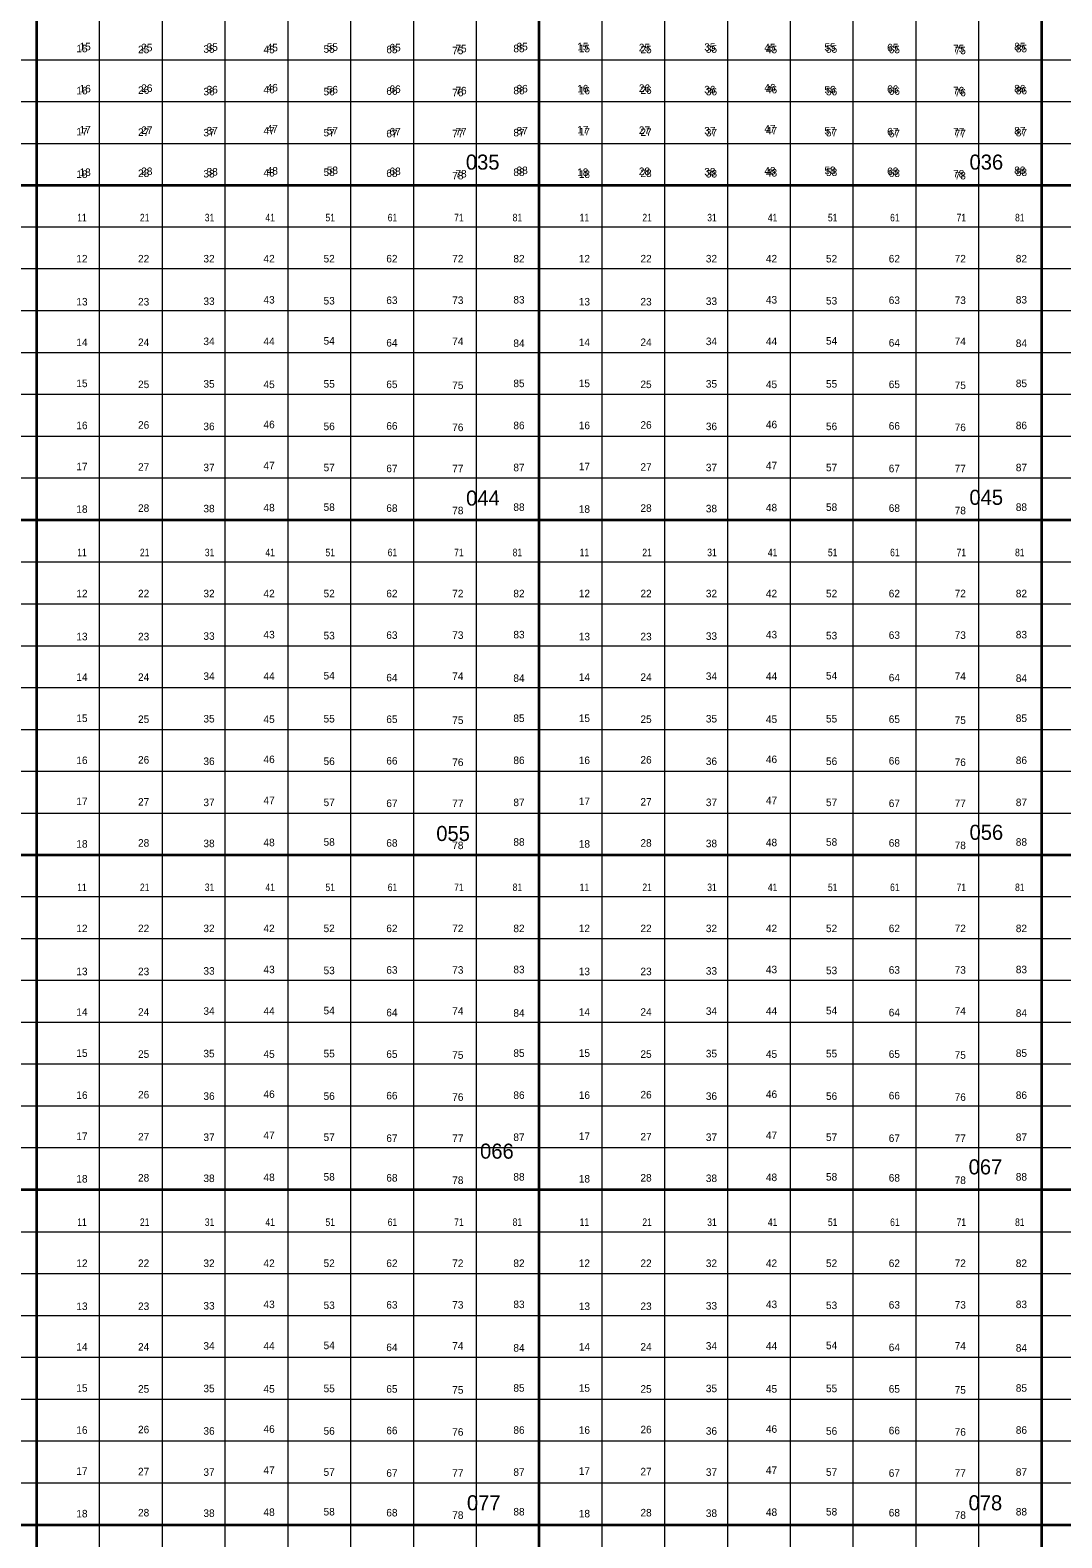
# Model space of a CAD drawing. Extents: x 639000 to 672000, y 222000 to 252000.
# Drawn here: x 647960 to 654120, y 233921 to 242926 of the extents above; entities that cross this region are included whole.
import ezdxf
from ezdxf.enums import TextEntityAlignment as Align

# ---------------------------------------------------------------- set-up
doc = ezdxf.new("R2010")
doc.units = 0
doc.header["$LTSCALE"] = 18
doc.layers.add('1', color=7, linetype='Continuous', lineweight=13)
doc.layers.add('2', color=7, linetype='Continuous')
doc.layers.add('29', color=7, linetype='Continuous')

msp = doc.modelspace()

# ---------------------------------------------------------------- linework, layer by layer
at = {"layer": '1', "lineweight": 35}
for p, q in [((648000, 224000), (648000, 252000)), ((651000, 224000), (651000, 252000)), ((654000, 222000), (654000, 252000)), ((639000, 242000), (672000, 242000)), ((672000, 240000), (639000, 240000)), ((639000, 238000), (672000, 238000)), ((672000, 236000), (639000, 236000)), ((639000, 234000), (672000, 234000))]:
    msp.add_line(p, q, dxfattribs=at)
at = {"layer": '1'}
for p, q in [((648375, 224000), (648375, 252000)), ((648750, 224000), (648750, 252000)), ((649125, 224000), (649125, 252000)), ((649500, 224000), (649500, 252000)), ((649875, 224000), (649875, 252000)), ((650250, 224000), (650250, 252000)), ((650625, 224000), (650625, 252000)), ((651375, 224000), (651375, 252000)), ((651750, 224000), (651750, 252000)), ((652125, 224000), (652125, 252000)), ((652500, 224000), (652500, 252000)), ((652875, 224000), (652875, 252000)), ((653250, 224000), (653250, 252000)), ((653625, 224000), (653625, 252000)), ((639000, 242750), (666000, 242750)), ((639000, 242500), (666000, 242500)), ((639000, 242250), (666000, 242250)), ((672000, 241750), (639000, 241750)), ((672000, 241500), (639000, 241500)), ((672000, 241250), (639000, 241250)), ((672000, 241000), (639000, 241000)), ((672000, 240750), (639000, 240750)), ((672000, 240500), (639000, 240500)), ((672000, 240250), (639000, 240250)), ((639000, 239750), (672000, 239750)), ((639000, 239500), (672000, 239500)), ((639000, 239250), (672000, 239250)), ((639000, 239000), (672000, 239000)), ((639000, 238750), (672000, 238750)), ((639000, 238500), (672000, 238500)), ((639000, 238250), (672000, 238250)), ((672000, 237750), (639000, 237750)), ((672000, 237500), (639000, 237500)), ((672000, 237250), (639000, 237250)), ((672000, 237000), (639000, 237000)), ((672000, 236750), (639000, 236750)), ((672000, 236500), (639000, 236500)), ((672000, 236250), (639000, 236250)), ((639000, 235750), (672000, 235750)), ((639000, 235500), (672000, 235500)), ((639000, 235250), (672000, 235250)), ((639000, 235000), (672000, 235000)), ((639000, 234750), (672000, 234750)), ((639000, 234500), (672000, 234500)), ((639000, 234250), (672000, 234250))]:
    msp.add_line(p, q, dxfattribs=at)

# ---------------------------------------------------------------- texts
at = {"layer": '2'}
for s, p in [('035', (650662.01, 242093.32)), ('055', (650485.32, 238083.33))]:
    msp.add_text(s, height=90, dxfattribs=at).set_placement(p, align=Align.CENTER)
for s, rotation, p in [('036', 359.94, (653669.39, 242093.33)), ('044', 0.36, (650663.7, 240086.93)), ('045', 359.94, (653668.72, 240091.12)), ('056', 359.94, (653669.39, 238090.28)), ('066', 359.94, (650746.84, 236186.08)), ('067', 359.94, (653664.01, 236092.18)), ('077', 359.94, (650668.28, 234085.86)), ('078', 359.94, (653663.61, 234085.86))]:
    msp.add_text(s, height=90, rotation=rotation, dxfattribs=at).set_placement(p, align=Align.CENTER)
at = {"layer": '29'}
for s, p in [('15', (648269.26, 242794.13)), ('15', (648288.31, 242805.68)), ('25', (648637.51, 242788.35)), ('25', (648656.57, 242799.9)), ('35', (649027.99, 242791.24)), ('35', (649047.04, 242802.79)), ('45', (649386.72, 242788.35)), ('45', (649405.77, 242799.9)), ('55', (649745.45, 242791.24)), ('55', (649764.5, 242802.79)), ('65', (650120.05, 242788.36)), ('65', (650139.11, 242799.9)), ('75', (650513.7, 242782.58)), ('75', (650532.76, 242794.13)), ('85', (650878.78, 242794.13)), ('85', (650897.84, 242805.68)), ('15', (651259.74, 242805.68)), ('15', (651269.26, 242794.13)), ('25', (651628, 242799.9)), ('25', (651637.51, 242788.35)), ('35', (652018.47, 242802.79)), ('35', (652027.99, 242791.24)), ('45', (652377.2, 242799.9)), ('45', (652386.72, 242788.35)), ('55', (652735.94, 242802.79)), ('55', (652745.45, 242791.24)), ('65', (653110.54, 242799.9)), ('65', (653120.05, 242788.36)), ('75', (653504.19, 242794.13)), ('75', (653513.7, 242782.58)), ('85', (653869.27, 242805.68)), ('85', (653878.78, 242794.13)), ('16', (648288.31, 242554.51)), ('26', (648656.57, 242557.4)), ('36', (649047.04, 242548.74)), ('46', (649386.72, 242548.74)), ('46', (649405.77, 242560.29)), ('56', (649764.5, 242548.74)), ('66', (650139.11, 242551.62)), ('86', (650897.84, 242554.51)), ('16', (651259.74, 242554.51)), ('26', (651628, 242557.4)), ('36', (652018.47, 242548.74)), ('46', (652377.2, 242560.29)), ('46', (652386.72, 242548.74)), ('56', (652735.94, 242548.74)), ('66', (653110.54, 242551.62)), ('86', (653869.27, 242554.51)), ('16', (648269.26, 242542.96)), ('26', (648637.51, 242545.85)), ('36', (649027.99, 242537.19)), ('56', (649745.45, 242537.19)), ('66', (650120.05, 242540.08)), ('76', (650513.7, 242531.42)), ('76', (650532.76, 242542.96)), ('86', (650878.78, 242542.96)), ('16', (651269.26, 242542.96)), ('26', (651637.51, 242545.85)), ('36', (652027.99, 242537.19)), ('56', (652745.45, 242537.19)), ('66', (653120.05, 242540.08)), ('76', (653504.19, 242542.96)), ('76', (653513.7, 242531.42)), ('86', (653878.78, 242542.96)), ('17', (648269.26, 242297.57)), ('17', (648288.31, 242309.12)), ('27', (648637.51, 242294.69)), ('27', (648656.57, 242306.23)), ('37', (649027.99, 242291.8)), ('37', (649047.04, 242303.35)), ('47', (649386.72, 242303.35)), ('47', (649405.77, 242314.9)), ('57', (649745.45, 242291.8)), ('57', (649764.5, 242303.35)), ('67', (650120.05, 242286.03)), ('67', (650139.11, 242297.57)), ('77', (650513.7, 242286.03)), ('77', (650532.76, 242297.57)), ('87', (650878.78, 242291.8)), ('87', (650897.84, 242303.35)), ('17', (651259.74, 242309.12)), ('17', (651269.26, 242297.57)), ('27', (651628, 242306.23)), ('27', (651637.51, 242294.69)), ('37', (652018.47, 242303.35)), ('37', (652027.99, 242291.8)), ('47', (652377.21, 242314.9)), ('47', (652386.72, 242303.35)), ('57', (652735.94, 242303.35)), ('57', (652745.45, 242291.8)), ('67', (653110.54, 242297.57)), ('67', (653120.05, 242286.03)), ('77', (653504.19, 242297.57)), ('77', (653513.7, 242286.03)), ('87', (653869.27, 242303.35)), ('87', (653878.78, 242291.8)), ('18', (648269.25, 242043.52)), ('18', (648288.31, 242055.07)), ('28', (648637.51, 242049.3)), ('28', (648656.57, 242060.84)), ('38', (649027.99, 242046.41)), ('38', (649047.04, 242057.96)), ('48', (649386.72, 242052.18)), ('48', (649405.77, 242063.73)), ('58', (649745.45, 242055.07)), ('58', (649764.5, 242066.62)), ('68', (650120.05, 242049.3)), ('68', (650139.11, 242060.84)), ('78', (650513.7, 242034.86)), ('78', (650532.76, 242046.41)), ('88', (650878.78, 242055.07)), ('88', (650897.84, 242066.62)), ('18', (651259.74, 242055.07)), ('18', (651269.25, 242043.52)), ('28', (651628, 242060.84)), ('28', (651637.51, 242049.3)), ('38', (652018.47, 242057.96)), ('38', (652027.99, 242046.41)), ('48', (652377.2, 242063.73)), ('48', (652386.72, 242052.18)), ('58', (652735.93, 242066.62)), ('58', (652745.45, 242055.07)), ('68', (653110.54, 242060.84)), ('68', (653120.05, 242049.3)), ('78', (653504.19, 242046.41)), ('78', (653513.7, 242034.86)), ('88', (653869.27, 242066.62)), ('88', (653878.78, 242055.07)), ('12', (648269.25, 241538.96)), ('22', (648637.51, 241538.96)), ('32', (649027.99, 241538.96)), ('42', (649386.72, 241538.96)), ('52', (649745.45, 241538.96)), ('62', (650120.05, 241538.96)), ('72', (650513.7, 241538.96)), ('82', (650878.78, 241538.96)), ('12', (651269.25, 241538.96)), ('22', (651637.51, 241538.96)), ('32', (652027.99, 241538.96)), ('42', (652386.72, 241538.96)), ('52', (652745.45, 241538.96)), ('62', (653120.05, 241538.96)), ('72', (653513.7, 241538.96)), ('82', (653878.78, 241538.96)), ('43', (649386.72, 241293.57)), ('53', (649745.45, 241287.8)), ('63', (650120.05, 241290.68)), ('73', (650513.7, 241290.68)), ('83', (650878.78, 241293.57)), ('43', (652386.72, 241293.57)), ('53', (652745.45, 241287.8)), ('63', (653120.05, 241290.68)), ('73', (653513.7, 241290.68)), ('83', (653878.78, 241293.57)), ('13', (648269.26, 241282.02)), ('23', (648637.51, 241282.02)), ('33', (649027.99, 241284.91)), ('13', (651269.26, 241282.02)), ('23', (651637.51, 241282.02)), ('33', (652027.99, 241284.91)), ('14', (648269.26, 241039.52)), ('24', (648637.51, 241039.52)), ('34', (649027.99, 241045.29)), ('44', (649386.72, 241045.29)), ('54', (649745.45, 241048.18)), ('64', (650120.05, 241036.63)), ('74', (650513.7, 241045.29)), ('84', (650878.78, 241033.74)), ('14', (651269.26, 241039.52)), ('24', (651637.51, 241039.52)), ('34', (652027.99, 241045.29)), ('44', (652386.72, 241045.29)), ('54', (652745.45, 241048.18)), ('64', (653120.05, 241036.63)), ('74', (653513.7, 241045.29)), ('84', (653878.78, 241033.74)), ('15', (648269.26, 240794.13)), ('25', (648637.51, 240788.35)), ('35', (649027.99, 240791.24)), ('45', (649386.72, 240788.35)), ('55', (649745.45, 240791.24)), ('65', (650120.05, 240788.36)), ('75', (650513.7, 240782.58)), ('85', (650878.78, 240794.13)), ('15', (651269.26, 240794.13)), ('25', (651637.51, 240788.35)), ('35', (652027.99, 240791.24)), ('45', (652386.72, 240788.35)), ('55', (652745.45, 240791.24)), ('65', (653120.05, 240788.36)), ('75', (653513.7, 240782.58)), ('85', (653878.78, 240794.13)), ('16', (648269.26, 240542.96)), ('26', (648637.51, 240545.85)), ('36', (649027.99, 240537.19)), ('46', (649386.72, 240548.74)), ('56', (649745.45, 240537.19)), ('66', (650120.05, 240540.08)), ('76', (650513.7, 240531.42)), ('86', (650878.78, 240542.96)), ('16', (651269.26, 240542.96)), ('26', (651637.51, 240545.85)), ('36', (652027.99, 240537.19)), ('46', (652386.72, 240548.74)), ('56', (652745.45, 240537.19)), ('66', (653120.05, 240540.08)), ('76', (653513.7, 240531.42)), ('86', (653878.78, 240542.96)), ('17', (648269.26, 240297.57)), ('47', (649386.72, 240303.35)), ('17', (651269.26, 240297.57)), ('47', (652386.72, 240303.35)), ('27', (648637.51, 240294.69)), ('37', (649027.99, 240291.8)), ('57', (649745.45, 240291.8)), ('67', (650120.05, 240286.03)), ('77', (650513.7, 240286.03)), ('87', (650878.78, 240291.8)), ('27', (651637.51, 240294.69)), ('37', (652027.99, 240291.8)), ('57', (652745.45, 240291.8)), ('67', (653120.05, 240286.03)), ('77', (653513.7, 240286.03)), ('87', (653878.78, 240291.8)), ('18', (648269.25, 240043.52)), ('28', (648637.51, 240049.3)), ('38', (649027.99, 240046.41)), ('48', (649386.72, 240052.18)), ('58', (649745.45, 240055.07)), ('68', (650120.05, 240049.3)), ('78', (650513.7, 240034.86)), ('88', (650878.78, 240055.07)), ('18', (651269.25, 240043.52)), ('28', (651637.51, 240049.3)), ('38', (652027.99, 240046.41)), ('48', (652386.72, 240052.18)), ('58', (652745.45, 240055.07)), ('68', (653120.05, 240049.3)), ('78', (653513.7, 240034.86)), ('88', (653878.78, 240055.07)), ('12', (648269.25, 239538.96)), ('22', (648637.51, 239538.96)), ('32', (649027.99, 239538.96)), ('42', (649386.72, 239538.96)), ('52', (649745.45, 239538.96)), ('62', (650120.05, 239538.96)), ('72', (650513.7, 239538.96)), ('82', (650878.78, 239538.96)), ('12', (651269.25, 239538.96)), ('22', (651637.51, 239538.96)), ('32', (652027.99, 239538.96)), ('42', (652386.72, 239538.96)), ('52', (652745.45, 239538.96)), ('62', (653120.05, 239538.96)), ('72', (653513.7, 239538.96)), ('82', (653878.78, 239538.96)), ('13', (648269.26, 239282.02)), ('23', (648637.51, 239282.02)), ('33', (649027.99, 239284.91)), ('43', (649386.72, 239293.57)), ('53', (649745.45, 239287.8)), ('63', (650120.05, 239290.68)), ('73', (650513.7, 239290.68)), ('83', (650878.78, 239293.57)), ('13', (651269.26, 239282.02)), ('23', (651637.51, 239282.02)), ('33', (652027.99, 239284.91)), ('43', (652386.72, 239293.57)), ('53', (652745.45, 239287.8)), ('63', (653120.05, 239290.68)), ('73', (653513.7, 239290.68)), ('83', (653878.78, 239293.57)), ('14', (648269.26, 239039.52)), ('24', (648637.51, 239039.52)), ('34', (649027.99, 239045.29)), ('44', (649386.72, 239045.29)), ('54', (649745.45, 239048.18)), ('64', (650120.05, 239036.63)), ('74', (650513.7, 239045.29)), ('14', (651269.26, 239039.52)), ('24', (651637.51, 239039.52)), ('34', (652027.99, 239045.29)), ('44', (652386.72, 239045.29)), ('54', (652745.45, 239048.18)), ('64', (653120.05, 239036.63)), ('74', (653513.7, 239045.29)), ('84', (650878.78, 239033.74)), ('84', (653878.78, 239033.74)), ('15', (648269.26, 238794.13)), ('25', (648637.51, 238788.35)), ('35', (649027.99, 238791.24)), ('45', (649386.72, 238788.35)), ('55', (649745.45, 238791.24)), ('65', (650120.05, 238788.36)), ('75', (650513.7, 238782.58)), ('85', (650878.78, 238794.13)), ('15', (651269.26, 238794.13)), ('25', (651637.51, 238788.35)), ('35', (652027.99, 238791.24)), ('45', (652386.72, 238788.35)), ('55', (652745.45, 238791.24)), ('65', (653120.05, 238788.36)), ('75', (653513.7, 238782.58)), ('85', (653878.78, 238794.13)), ('16', (648269.26, 238542.96)), ('26', (648637.51, 238545.85)), ('36', (649027.99, 238537.19)), ('46', (649386.72, 238548.74)), ('56', (649745.45, 238537.19)), ('66', (650120.05, 238540.08)), ('76', (650513.7, 238531.42)), ('86', (650878.78, 238542.96)), ('16', (651269.26, 238542.96)), ('26', (651637.51, 238545.85)), ('36', (652027.99, 238537.19)), ('46', (652386.72, 238548.74)), ('56', (652745.45, 238537.19)), ('66', (653120.05, 238540.08)), ('76', (653513.7, 238531.42)), ('86', (653878.78, 238542.96)), ('17', (648269.26, 238297.57)), ('27', (648637.51, 238294.69)), ('37', (649027.99, 238291.8)), ('47', (649386.72, 238303.35)), ('57', (649745.45, 238291.8)), ('67', (650120.05, 238286.03)), ('77', (650513.7, 238286.03)), ('87', (650878.78, 238291.8)), ('17', (651269.26, 238297.57)), ('27', (651637.51, 238294.69)), ('37', (652027.99, 238291.8)), ('47', (652386.72, 238303.35)), ('57', (652745.45, 238291.8)), ('67', (653120.05, 238286.03)), ('77', (653513.7, 238286.03)), ('87', (653878.78, 238291.8)), ('28', (648637.51, 238049.3)), ('38', (649027.99, 238046.41)), ('48', (649386.72, 238052.18)), ('58', (649745.45, 238055.07)), ('68', (650120.05, 238049.3)), ('88', (650878.78, 238055.07)), ('28', (651637.51, 238049.3)), ('38', (652027.99, 238046.41)), ('48', (652386.72, 238052.18)), ('58', (652745.45, 238055.07)), ('68', (653120.05, 238049.3)), ('88', (653878.78, 238055.07)), ('18', (648269.25, 238043.52)), ('78', (650513.7, 238034.86)), ('18', (651269.25, 238043.52)), ('78', (653513.7, 238034.86)), ('12', (648269.25, 237538.96)), ('22', (648637.51, 237538.96)), ('32', (649027.99, 237538.96)), ('42', (649386.72, 237538.96)), ('52', (649745.45, 237538.96)), ('62', (650120.05, 237538.96)), ('72', (650513.7, 237538.96)), ('82', (650878.78, 237538.96)), ('12', (651269.25, 237538.96)), ('22', (651637.51, 237538.96)), ('32', (652027.99, 237538.96)), ('42', (652386.72, 237538.96)), ('52', (652745.45, 237538.96)), ('62', (653120.05, 237538.96)), ('72', (653513.7, 237538.96)), ('82', (653878.78, 237538.96)), ('13', (648269.26, 237282.02)), ('23', (648637.51, 237282.02)), ('33', (649027.99, 237284.91)), ('43', (649386.72, 237293.57)), ('53', (649745.45, 237287.8)), ('63', (650120.05, 237290.68)), ('73', (650513.7, 237290.68)), ('83', (650878.78, 237293.57)), ('13', (651269.26, 237282.02)), ('23', (651637.51, 237282.02)), ('33', (652027.99, 237284.91)), ('43', (652386.72, 237293.57)), ('53', (652745.45, 237287.8)), ('63', (653120.05, 237290.68)), ('73', (653513.7, 237290.68)), ('83', (653878.78, 237293.57)), ('14', (648269.26, 237039.52)), ('24', (648637.51, 237039.52)), ('34', (649027.99, 237045.29)), ('44', (649386.72, 237045.29)), ('54', (649745.45, 237048.18)), ('64', (650120.05, 237036.63)), ('74', (650513.7, 237045.29)), ('84', (650878.78, 237033.74)), ('14', (651269.26, 237039.52)), ('24', (651637.51, 237039.52)), ('34', (652027.99, 237045.29)), ('44', (652386.72, 237045.29)), ('54', (652745.45, 237048.18)), ('64', (653120.05, 237036.63)), ('74', (653513.7, 237045.29)), ('84', (653878.78, 237033.74)), ('15', (648269.26, 236794.13)), ('25', (648637.51, 236788.35)), ('35', (649027.99, 236791.24)), ('45', (649386.72, 236788.35)), ('55', (649745.45, 236791.24)), ('65', (650120.05, 236788.36)), ('85', (650878.78, 236794.13)), ('15', (651269.26, 236794.13)), ('25', (651637.51, 236788.35)), ('35', (652027.99, 236791.24)), ('45', (652386.72, 236788.35)), ('55', (652745.45, 236791.24)), ('65', (653120.05, 236788.36)), ('85', (653878.78, 236794.13)), ('75', (650513.7, 236782.58)), ('75', (653513.7, 236782.58)), ('16', (648269.26, 236542.96)), ('26', (648637.51, 236545.85)), ('36', (649027.99, 236537.19)), ('46', (649386.72, 236548.74)), ('56', (649745.45, 236537.19)), ('66', (650120.05, 236540.08)), ('76', (650513.7, 236531.42)), ('86', (650878.78, 236542.96)), ('16', (651269.26, 236542.96)), ('26', (651637.51, 236545.85)), ('36', (652027.99, 236537.19)), ('46', (652386.72, 236548.74)), ('56', (652745.45, 236537.19)), ('66', (653120.05, 236540.08)), ('76', (653513.7, 236531.42)), ('86', (653878.78, 236542.96)), ('17', (648269.26, 236297.57)), ('27', (648637.51, 236294.69)), ('37', (649027.99, 236291.8)), ('47', (649386.72, 236303.35)), ('57', (649745.45, 236291.8)), ('67', (650120.05, 236286.03)), ('77', (650513.7, 236286.03)), ('87', (650878.78, 236291.8)), ('17', (651269.26, 236297.57)), ('27', (651637.51, 236294.69)), ('37', (652027.99, 236291.8)), ('47', (652386.72, 236303.35)), ('57', (652745.45, 236291.8)), ('67', (653120.05, 236286.03)), ('77', (653513.7, 236286.03)), ('87', (653878.78, 236291.8)), ('18', (648269.25, 236043.52)), ('28', (648637.51, 236049.3)), ('38', (649027.99, 236046.41)), ('48', (649386.72, 236052.18)), ('58', (649745.45, 236055.07)), ('68', (650120.05, 236049.3)), ('78', (650513.7, 236034.86)), ('88', (650878.78, 236055.07)), ('18', (651269.25, 236043.52)), ('28', (651637.51, 236049.3)), ('38', (652027.99, 236046.41)), ('48', (652386.72, 236052.18)), ('58', (652745.45, 236055.07)), ('68', (653120.05, 236049.3)), ('78', (653513.7, 236034.86)), ('88', (653878.78, 236055.07)), ('12', (648269.25, 235538.96)), ('22', (648637.51, 235538.96)), ('32', (649027.99, 235538.96)), ('42', (649386.72, 235538.96)), ('52', (649745.45, 235538.96)), ('62', (650120.05, 235538.96)), ('72', (650513.7, 235538.96)), ('82', (650878.78, 235538.96)), ('12', (651269.25, 235538.96)), ('22', (651637.51, 235538.96)), ('32', (652027.99, 235538.96)), ('42', (652386.72, 235538.96)), ('52', (652745.45, 235538.96)), ('62', (653120.05, 235538.96)), ('72', (653513.7, 235538.96)), ('82', (653878.78, 235538.96)), ('13', (648269.26, 235282.02)), ('23', (648637.51, 235282.02)), ('33', (649027.99, 235284.91)), ('43', (649386.72, 235293.57)), ('53', (649745.45, 235287.8)), ('63', (650120.05, 235290.68)), ('73', (650513.7, 235290.68)), ('83', (650878.78, 235293.57)), ('13', (651269.26, 235282.02)), ('23', (651637.51, 235282.02)), ('33', (652027.99, 235284.91)), ('43', (652386.72, 235293.57)), ('53', (652745.45, 235287.8)), ('63', (653120.05, 235290.68)), ('73', (653513.7, 235290.68)), ('83', (653878.78, 235293.57)), ('14', (648269.26, 235039.52)), ('24', (648637.51, 235039.52)), ('34', (649027.99, 235045.29)), ('44', (649386.72, 235045.29)), ('54', (649745.45, 235048.18)), ('64', (650120.05, 235036.63)), ('74', (650513.7, 235045.29)), ('84', (650878.78, 235033.74)), ('14', (651269.26, 235039.52)), ('24', (651637.51, 235039.52)), ('34', (652027.99, 235045.29)), ('44', (652386.72, 235045.29)), ('54', (652745.45, 235048.18)), ('64', (653120.05, 235036.63)), ('74', (653513.7, 235045.29)), ('84', (653878.78, 235033.74)), ('15', (648269.26, 234794.13)), ('25', (648637.51, 234788.35)), ('35', (649027.99, 234791.24)), ('45', (649386.72, 234788.35)), ('55', (649745.45, 234791.24)), ('65', (650120.05, 234788.36)), ('75', (650513.7, 234782.58)), ('85', (650878.78, 234794.13)), ('15', (651269.26, 234794.13)), ('25', (651637.51, 234788.35)), ('35', (652027.99, 234791.24)), ('45', (652386.72, 234788.35)), ('55', (652745.45, 234791.24)), ('65', (653120.05, 234788.36)), ('75', (653513.7, 234782.58)), ('85', (653878.78, 234794.13)), ('16', (648269.26, 234542.96)), ('26', (648637.51, 234545.85)), ('36', (649027.99, 234537.19)), ('46', (649386.72, 234548.74)), ('56', (649745.45, 234537.19)), ('66', (650120.05, 234540.08)), ('86', (650878.78, 234542.96)), ('16', (651269.26, 234542.96)), ('26', (651637.51, 234545.85)), ('36', (652027.99, 234537.19)), ('46', (652386.72, 234548.74)), ('56', (652745.45, 234537.19)), ('66', (653120.05, 234540.08)), ('86', (653878.78, 234542.96)), ('76', (650513.7, 234531.42)), ('76', (653513.7, 234531.42)), ('17', (648269.26, 234297.57)), ('27', (648637.51, 234294.69)), ('37', (649027.99, 234291.8)), ('47', (649386.72, 234303.35)), ('57', (649745.45, 234291.8)), ('67', (650120.05, 234286.03)), ('77', (650513.7, 234286.03)), ('87', (650878.78, 234291.8)), ('17', (651269.26, 234297.57)), ('27', (651637.51, 234294.69)), ('37', (652027.99, 234291.8)), ('47', (652386.72, 234303.35)), ('57', (652745.45, 234291.8)), ('67', (653120.05, 234286.03)), ('77', (653513.7, 234286.03)), ('87', (653878.78, 234291.8)), ('18', (648269.25, 234043.52)), ('28', (648637.51, 234049.3)), ('38', (649027.99, 234046.41)), ('48', (649386.72, 234052.18)), ('58', (649745.45, 234055.07)), ('68', (650120.05, 234049.3)), ('78', (650513.7, 234034.86)), ('88', (650878.78, 234055.07)), ('18', (651269.25, 234043.52)), ('28', (651637.51, 234049.3)), ('38', (652027.99, 234046.41)), ('48', (652386.72, 234052.18)), ('58', (652745.45, 234055.07)), ('68', (653120.05, 234049.3)), ('78', (653513.7, 234034.86)), ('88', (653878.78, 234055.07))]:
    msp.add_text(s, height=45, dxfattribs=at).set_placement(p, align=Align.CENTER)
at = {"layer": '29', "width": 0.85}
for s, p in [('11', (648269.26, 241784.35)), ('21', (648643.86, 241784.35)), ('31', (649031.16, 241784.35)), ('41', (649393.07, 241784.35)), ('51', (649751.8, 241784.35)), ('61', (650123.23, 241784.35)), ('71', (650520.05, 241784.35)), ('81', (650869.26, 241784.35)), ('11', (651269.26, 241784.35)), ('21', (651643.86, 241784.35)), ('31', (652031.16, 241784.35)), ('41', (652393.07, 241784.35)), ('51', (652751.8, 241784.35)), ('61', (653123.23, 241784.35)), ('71', (653520.05, 241784.35)), ('81', (653869.26, 241784.35)), ('11', (648269.26, 239784.35)), ('21', (648643.86, 239784.35)), ('31', (649031.16, 239784.35)), ('41', (649393.07, 239784.35)), ('51', (649751.8, 239784.35)), ('61', (650123.23, 239784.35)), ('71', (650520.05, 239784.35)), ('81', (650869.26, 239784.35)), ('11', (651269.26, 239784.35)), ('21', (651643.86, 239784.35)), ('31', (652031.16, 239784.35)), ('41', (652393.07, 239784.35)), ('51', (652751.8, 239784.35)), ('61', (653123.23, 239784.35)), ('71', (653520.05, 239784.35)), ('81', (653869.26, 239784.35)), ('11', (648269.26, 237784.35)), ('21', (648643.86, 237784.35)), ('31', (649031.16, 237784.35)), ('41', (649393.07, 237784.35)), ('51', (649751.8, 237784.35)), ('61', (650123.23, 237784.35)), ('71', (650520.05, 237784.35)), ('81', (650869.26, 237784.35)), ('11', (651269.26, 237784.35)), ('21', (651643.86, 237784.35)), ('31', (652031.16, 237784.35)), ('41', (652393.07, 237784.35)), ('51', (652751.8, 237784.35)), ('61', (653123.23, 237784.35)), ('71', (653520.05, 237784.35)), ('81', (653869.26, 237784.35)), ('11', (648269.26, 235784.35)), ('21', (648643.86, 235784.35)), ('31', (649031.16, 235784.35)), ('41', (649393.07, 235784.35)), ('51', (649751.8, 235784.35)), ('61', (650123.23, 235784.35)), ('71', (650520.05, 235784.35)), ('81', (650869.26, 235784.35)), ('11', (651269.26, 235784.35)), ('21', (651643.86, 235784.35)), ('31', (652031.16, 235784.35)), ('41', (652393.07, 235784.35)), ('51', (652751.8, 235784.35)), ('61', (653123.23, 235784.35)), ('71', (653520.05, 235784.35)), ('81', (653869.26, 235784.35))]:
    msp.add_text(s, height=45, dxfattribs=at).set_placement(p, align=Align.CENTER)

doc.saveas('drawing.dxf')
